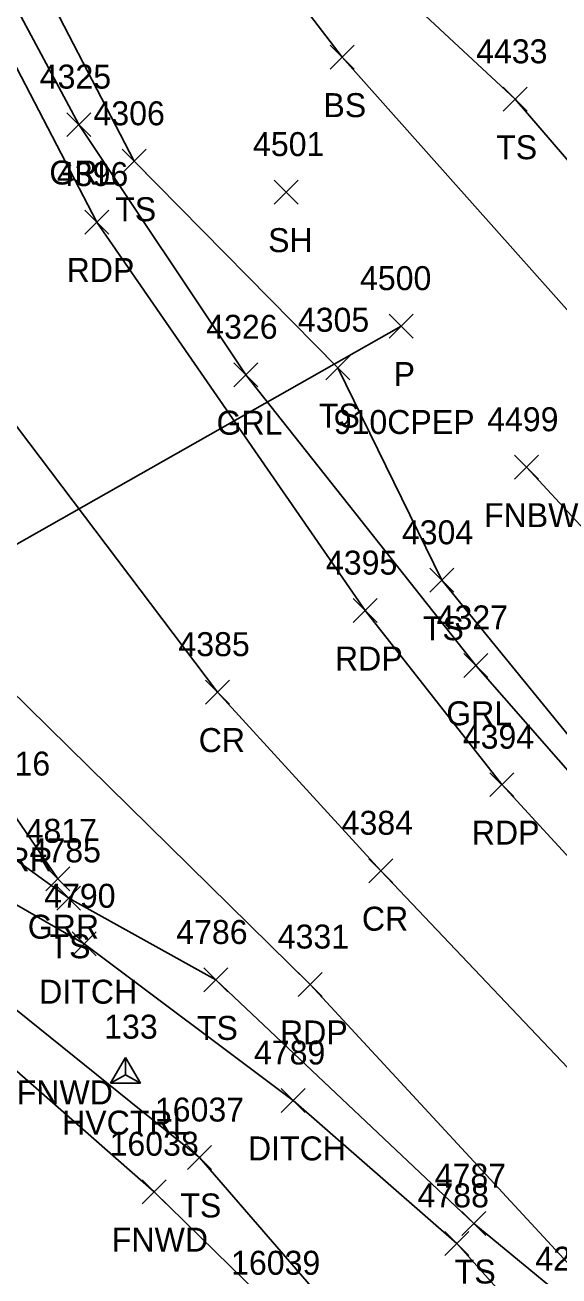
# Model space of a CAD drawing. Extents: x 1482574 to 1485769, y 580696 to 595649.
# Drawn here: x 1483589.1 to 1483633.6, y 583487.9 to 583592.2 of the extents above; entities that cross this region are included whole.
import ezdxf

# ---------------------------------------------------------------- set-up
doc = ezdxf.new("R2010")
doc.units = 0
for name, color, linetype in [('C_A', 7, 'Continuous'), ('C_I', 7, 'Continuous'), ('CPSM', 7, 'Continuous'), ('D_A', 7, 'Continuous'), ('D_C', 7, 'Continuous'), ('D_I', 7, 'Continuous'), ('D_TIC', 7, 'Continuous'), ('DCP', 7, 'Continuous'), ('DD', 7, 'Continuous'), ('L_A', 7, 'Continuous'), ('L_C', 7, 'Continuous'), ('L_I', 7, 'Continuous'), ('L_TIC', 7, 'Continuous'), ('LELB', 7, 'Continuous'), ('LFNC', 7, 'Continuous'), ('P_A', 7, 'Continuous'), ('P_I', 7, 'Continuous'), ('P_TIC', 7, 'Continuous'), ('PET', 7, 'Continuous'), ('PRC', 7, 'Continuous'), ('R_A', 7, 'Continuous'), ('R_I', 7, 'Continuous'), ('R_TIC', 7, 'Continuous'), ('RGR', 7, 'Continuous'), ('U_I', 7, 'Continuous')]:
    doc.layers.add(name, color=color, linetype=linetype)

msp = doc.modelspace()

# ---------------------------------------------------------------- linework, layer by layer
at = {"layer": 'CPSM'}
for p, q in [((1483596.21, 583503.94), (1483597.46, 583506.1)), ((1483598.71, 583503.94), (1483597.46, 583506.1)), ((1483597.46, 583504.66), (1483597.46, 583506.1)), ((1483596.21, 583503.94), (1483597.46, 583504.66)), ((1483597.46, 583504.66), (1483597.46, 583504.66)), ((1483597.46, 583504.66), (1483598.71, 583503.94)), ((1483596.21, 583503.94), (1483598.71, 583503.94))]:
    msp.add_line(p, q, dxfattribs=at)
at = {"layer": 'D_TIC'}
for points in [[(1483619.43, 583566.1), (1483621.43, 583568.1)], [(1483621.43, 583566.1), (1483619.43, 583568.1)], [(1483593.01, 583514.58), (1483595.01, 583516.58)], [(1483595.01, 583514.58), (1483593.01, 583516.58)], [(1483610.42, 583501.51), (1483612.42, 583503.51)], [(1483612.42, 583501.51), (1483610.42, 583503.51)], [(1483624.06, 583489.59), (1483626.06, 583491.59)], [(1483626.06, 583489.59), (1483624.06, 583491.59)]]:
    msp.add_lwpolyline(points, dxfattribs=at)
at = {"layer": 'DCP'}
msp.add_lwpolyline([(1483620.43, 583567.1), (1483559.02, 583532.26)], dxfattribs=at)
at = {"layer": 'DD'}
for points in [[(1483625.06, 583490.59), (1483611.42, 583502.51), (1483594.01, 583515.58), (1483579.6, 583523.87), (1483563.63, 583528.81)], [(1483625.06, 583490.59), (1483632.21, 583482.59)]]:
    msp.add_lwpolyline(points, dxfattribs=at)
at = {"layer": 'L_TIC'}
for points in [[(1483614.51, 583588.53), (1483616.51, 583590.53)], [(1483616.51, 583588.53), (1483614.51, 583590.53)], [(1483628.94, 583585.02), (1483630.94, 583587.02)], [(1483630.94, 583585.02), (1483628.94, 583587.02)], [(1483597.18, 583579.85), (1483599.18, 583581.85)], [(1483599.18, 583579.85), (1483597.18, 583581.85)], [(1483609.85, 583577.28), (1483611.85, 583579.27)], [(1483611.85, 583577.28), (1483609.85, 583579.27)], [(1483614.16, 583562.63), (1483616.16, 583564.63)], [(1483616.16, 583562.63), (1483614.16, 583564.63)], [(1483629.87, 583554.33), (1483631.87, 583556.33)], [(1483631.87, 583554.33), (1483629.87, 583556.33)], [(1483622.83, 583544.9), (1483624.83, 583546.9)], [(1483624.83, 583544.9), (1483622.83, 583546.9)], [(1483591.71, 583518.37), (1483593.7, 583520.37)], [(1483593.7, 583518.37), (1483591.71, 583520.37)], [(1483603.99, 583511.56), (1483605.99, 583513.56)], [(1483605.99, 583511.56), (1483603.99, 583513.56)], [(1483602.61, 583496.75), (1483604.61, 583498.75)], [(1483604.61, 583496.75), (1483602.61, 583498.75)], [(1483598.84, 583493.9), (1483600.84, 583495.9)], [(1483600.84, 583493.9), (1483598.84, 583495.9)], [(1483625.49, 583491.24), (1483627.49, 583493.24)], [(1483627.49, 583491.24), (1483625.49, 583493.24)]]:
    msp.add_lwpolyline(points, dxfattribs=at)
at = {"layer": 'LELB'}
for points in [[(1483638.18, 583528.29), (1483623.83, 583545.9), (1483615.16, 583563.63), (1483598.18, 583580.85), (1483584.91, 583606.41), (1483576.29, 583635.39), (1483571.8, 583664.7), (1483567.86, 583692.01), (1483571.37, 583722.39), (1483575.73, 583749.31), (1483582.05, 583780.14), (1483587.02, 583800.96), (1483586.5, 583812.63)], [(1483741.79, 583540.7), (1483726.53, 583544.33), (1483704.06, 583547.16), (1483680.39, 583551.44), (1483644.49, 583569.09), (1483629.94, 583586.02), (1483612.61, 583602.16), (1483600.95, 583609.44)], [(1483735.81, 583533.58), (1483716.93, 583528.46), (1483698.46, 583520.38), (1483684.11, 583529.64), (1483670.36, 583539.06), (1483646, 583555.28), (1483615.51, 583589.53), (1483606.5, 583601.33)], [(1483544.26, 583539.63), (1483551.86, 583545.22), (1483560.07, 583540.8), (1483564.9, 583533.33), (1483582.58, 583526.7), (1483592.71, 583519.37), (1483604.99, 583512.56), (1483626.49, 583492.24)], [(1483559.24, 583520.5), (1483573.36, 583521.39), (1483583.54, 583513.9), (1483603.61, 583497.75), (1483618.64, 583480.38)], [(1483626.49, 583492.24), (1483634.88, 583485.31)]]:
    msp.add_lwpolyline(points, dxfattribs=at)
at = {"layer": 'LFNC'}
for points in [[(1483673.76, 583527.84), (1483658.85, 583526.6), (1483644.31, 583540.81), (1483630.87, 583555.33)], [(1483563.31, 583514.81), (1483573.03, 583517.54), (1483581.28, 583511.18), (1483599.84, 583494.9), (1483609.97, 583484.97), (1483617.31, 583477.83)]]:
    msp.add_lwpolyline(points, dxfattribs=at)
at = {"layer": 'P_TIC'}
for points in [[(1483594.05, 583574.78), (1483596.05, 583576.78)], [(1483596.05, 583574.78), (1483594.05, 583576.78)], [(1483616.42, 583542.37), (1483618.42, 583544.37)], [(1483618.42, 583542.37), (1483616.42, 583544.37)], [(1483604.12, 583535.57), (1483606.12, 583537.57)], [(1483606.12, 583535.57), (1483604.12, 583537.57)], [(1483627.83, 583527.85), (1483629.83, 583529.85)], [(1483629.83, 583527.85), (1483627.83, 583529.85)], [(1483617.73, 583520.67), (1483619.73, 583522.67)], [(1483619.73, 583520.67), (1483617.73, 583522.67)], [(1483611.84, 583511.18), (1483613.84, 583513.18)], [(1483613.84, 583511.18), (1483611.84, 583513.18)]]:
    msp.add_lwpolyline(points, dxfattribs=at)
at = {"layer": 'PET'}
for points in [[(1483628.83, 583528.85), (1483617.42, 583543.37), (1483595.05, 583575.78), (1483578.7, 583607.28), (1483568.42, 583641.78), (1483564.67, 583676.42), (1483566.47, 583711.48), (1483571.17, 583746.23), (1483573.69, 583780.53), (1483577.92, 583804.21)], [(1483734.47, 583384.83), (1483710.77, 583410.08), (1483685.69, 583436.09), (1483659.83, 583462.34), (1483636.38, 583486.71), (1483612.84, 583512.18), (1483585.95, 583538.63), (1483563.03, 583563.69), (1483555.97, 583565.92)], [(1483628.83, 583528.85), (1483657.83, 583497.29)]]:
    msp.add_lwpolyline(points, dxfattribs=at)
at = {"layer": 'PRC'}
for points in [[(1483618.73, 583521.67), (1483605.12, 583536.57), (1483580.09, 583569.69), (1483562.2, 583601.73), (1483551.28, 583637.89), (1483548.66, 583672.74), (1483550.4, 583708.14), (1483555.34, 583744.78), (1483561.11, 583779.91), (1483565.84, 583808.31), (1483572.09, 583842.87), (1483580.82, 583892.49), (1483589.4, 583942.82)], [(1483618.73, 583521.67), (1483644.72, 583494.27)]]:
    msp.add_lwpolyline(points, dxfattribs=at)
at = {"layer": 'R_TIC'}
for points in [[(1483592.55, 583582.91), (1483594.55, 583584.9)], [(1483594.55, 583582.91), (1483592.55, 583584.9)], [(1483606.49, 583562.04), (1483608.49, 583564.04)], [(1483608.49, 583562.04), (1483606.49, 583564.04)], [(1483625.65, 583537.8), (1483627.65, 583539.8)], [(1483627.65, 583537.8), (1483625.65, 583539.8)], [(1483590.81, 583520), (1483592.81, 583522)], [(1483592.81, 583520), (1483590.81, 583522)]]:
    msp.add_lwpolyline(points, dxfattribs=at)
at = {"layer": 'RGR'}
for points in [[(1483584.85, 583800.99), (1483581.02, 583785.39), (1483576.51, 583765.04), (1483571.73, 583733.99), (1483567.7, 583702.98), (1483566.07, 583678.04), (1483568.17, 583653.2), (1483573.19, 583628.8), (1483581.79, 583605.84), (1483593.55, 583583.91), (1483607.49, 583563.04), (1483626.65, 583538.8), (1483647.15, 583515.42), (1483656.3, 583506.85), (1483665.83, 583498.69)], [(1483536.41, 583543.11), (1483536.54, 583552.4), (1483541.8, 583558.71), (1483550.74, 583560.91), (1483558.43, 583558.54), (1483565.89, 583551.76), (1483572.11, 583545.67), (1483578, 583539.33), (1483583.44, 583532.55), (1483587.97, 583526.61), (1483591.81, 583521)]]:
    msp.add_lwpolyline(points, dxfattribs=at)

# ---------------------------------------------------------------- texts
at = {"layer": 'C_A'}
msp.add_text('HVCTRL', height=2, dxfattribs=at).set_placement((1483592.16, 583499.66))
at = {"layer": 'C_I'}
msp.add_text('133', height=2, dxfattribs=at).set_placement((1483595.67, 583507.66))
at = {"layer": 'D_A'}
for s, p in [('P', (1483619.8, 583562.1)), ('DITCH', (1483590.25, 583510.58)), ('DITCH', (1483607.66, 583497.51))]:
    msp.add_text(s, height=2, dxfattribs=at).set_placement(p)
at = {"layer": 'D_C'}
msp.add_text('910CPEP', height=2, dxfattribs=at).set_placement((1483614.81, 583558.1))
at = {"layer": 'D_I'}
for s, p in [('4500', (1483617, 583570.1)), ('4790', (1483590.67, 583518.58)), ('4789', (1483608.16, 583505.51)), ('4788', (1483621.8, 583493.59))]:
    msp.add_text(s, height=2, dxfattribs=at).set_placement(p)
at = {"layer": 'L_A'}
for s, p in [('BS', (1483613.95, 583584.53)), ('TS', (1483628.35, 583581.02)), ('TS', (1483596.59, 583575.85)), ('SH', (1483609.34, 583573.27)), ('TS', (1483613.57, 583558.63)), ('FNBW', (1483627.34, 583550.33)), ('TS', (1483622.24, 583540.9)), ('TS', (1483591.11, 583514.37)), ('TS', (1483603.4, 583507.56)), ('TS', (1483602.02, 583492.75)), ('FNWD', (1483596.31, 583489.9)), ('TS', (1483624.9, 583487.24))]:
    msp.add_text(s, height=2, dxfattribs=at).set_placement(p)
at = {"layer": 'L_C'}
msp.add_text('SEPTIC FOLLOWS FNWD', height=2, dxfattribs=at).set_placement((1483564.15, 583502.18))
at = {"layer": 'L_I'}
for s, p in [('4433', (1483626.68, 583589.02)), ('4306', (1483594.78, 583583.85)), ('4501', (1483608.08, 583581.28)), ('4305', (1483611.82, 583566.63)), ('4499', (1483627.6, 583558.33)), ('4304', (1483620.49, 583548.9)), ('4785', (1483589.45, 583522.37)), ('4786', (1483601.68, 583515.56)), ('16037', (1483599.9, 583500.75)), ('16038', (1483596.12, 583497.9)), ('4787', (1483623.23, 583495.24)), ('16039', (1483606.25, 583487.97)), ('4222', (1483631.62, 583488.31))]:
    msp.add_text(s, height=2, dxfattribs=at).set_placement(p)
at = {"layer": 'P_A'}
for s, p in [('RDP', (1483592.54, 583570.78)), ('RDP', (1483614.91, 583538.37)), ('CR', (1483603.55, 583531.57)), ('RDP', (1483626.32, 583523.85)), ('CR', (1483617.16, 583516.67)), ('RDP', (1483610.33, 583507.18))]:
    msp.add_text(s, height=2, dxfattribs=at).set_placement(p)
at = {"layer": 'P_I'}
for s, p in [('4396', (1483591.73, 583578.78)), ('4395', (1483614.16, 583546.37)), ('4385', (1483601.86, 583539.57)), ('4394', (1483625.57, 583531.85)), ('4384', (1483615.47, 583524.67)), ('4331', (1483610.14, 583515.18))]:
    msp.add_text(s, height=2, dxfattribs=at).set_placement(p)
at = {"layer": 'R_A'}
for s, p in [('GRL', (1483591.1, 583578.91)), ('GRL', (1483605.04, 583558.04)), ('GRL', (1483624.19, 583533.8)), ('GRR', (1483585.45, 583521.61)), ('GRR', (1483589.3, 583516))]:
    msp.add_text(s, height=2, dxfattribs=at).set_placement(p)
at = {"layer": 'R_I'}
for s, p in [('4325', (1483590.3, 583586.91)), ('4326', (1483604.18, 583566.04)), ('4327', (1483623.39, 583541.8)), ('4816', (1483585.22, 583529.61)), ('4817', (1483589.12, 583524))]:
    msp.add_text(s, height=2, dxfattribs=at).set_placement(p)
at = {"layer": 'U_I'}
msp.add_text('16039', height=2, dxfattribs=at).set_placement((1483606.25, 583487.97))

doc.saveas('drawing.dxf')
